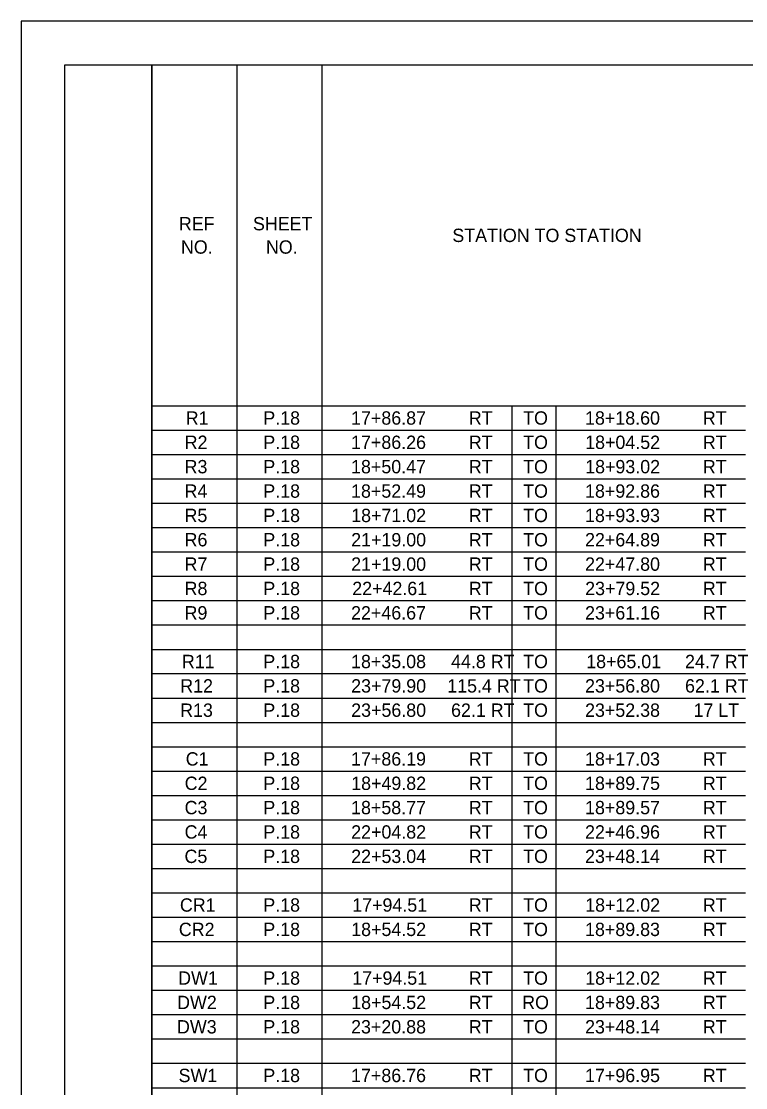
# Model space of a CAD drawing. Extents: x 0 to 34, y 0 to 22.
# Drawn here: x 0 to 8.32, y 9.75 to 22 of the extents above; entities that cross this region are included whole.
import ezdxf

# ---------------------------------------------------------------- set-up
doc = ezdxf.new("R2010")
doc.units = 0
for name, color, linetype in [('Default', 7, 'Continuous'), ('SH_Border', 7, 'Continuous'), ('SH_Cut_Line', 7, 'Continuous')]:
    doc.layers.add(name, color=color, linetype=linetype)

msp = doc.modelspace()

# ---------------------------------------------------------------- linework, layer by layer
at = {"layer": 'Default'}
for p, q in [((1.5, 21.5), (4.884, 21.5)), ((1.5, 21.5), (1.5, 21.22)), ((2.476, 21.5), (2.476, 21.22)), ((3.452, 21.5), (3.452, 21.22)), ((4.884, 21.5), (5.631, 21.5)), ((5.631, 21.5), (8.318, 21.5)), ((1.5, 21.22), (1.5, 20.941)), ((2.476, 21.22), (2.476, 20.941)), ((3.452, 21.22), (3.452, 20.941)), ((1.5, 20.941), (1.5, 20.661)), ((2.476, 20.941), (2.476, 20.661)), ((3.452, 20.941), (3.452, 20.661)), ((1.5, 20.661), (1.5, 20.381)), ((2.476, 20.661), (2.476, 20.381)), ((3.452, 20.661), (3.452, 20.381)), ((1.5, 20.381), (1.5, 20.101)), ((2.476, 20.381), (2.476, 20.101)), ((3.452, 20.381), (3.452, 20.101)), ((1.5, 20.101), (1.5, 19.822)), ((2.476, 20.101), (2.476, 19.822)), ((3.452, 20.101), (3.452, 19.822)), ((1.5, 19.822), (1.5, 19.542)), ((2.476, 19.822), (2.476, 19.542)), ((3.452, 19.822), (3.452, 19.542)), ((1.5, 19.542), (1.5, 18.982)), ((2.476, 19.542), (2.476, 18.982)), ((3.452, 19.542), (3.452, 18.982)), ((1.5, 18.982), (1.5, 18.143)), ((2.476, 18.982), (2.476, 18.143)), ((3.452, 18.982), (3.452, 18.143)), ((1.5, 18.143), (1.5, 17.864)), ((2.476, 18.143), (2.476, 17.864)), ((3.452, 18.143), (3.452, 17.864)), ((1.5, 17.864), (1.5, 17.304)), ((2.476, 17.864), (2.476, 17.304)), ((3.452, 17.864), (3.452, 17.304)), ((1.5, 17.584), (4.884, 17.584)), ((4.884, 17.584), (5.631, 17.584)), ((5.631, 17.584), (8.318, 17.584)), ((5.631, 17.584), (5.631, 17.304)), ((6.138, 17.584), (6.138, 17.304)), ((1.5, 17.304), (4.884, 17.304)), ((1.5, 17.304), (1.5, 17.024)), ((2.476, 17.304), (2.476, 17.024)), ((3.452, 17.304), (3.452, 17.024)), ((4.884, 17.304), (5.631, 17.304)), ((5.631, 17.304), (8.318, 17.304)), ((5.631, 17.304), (5.631, 17.024)), ((6.138, 17.304), (6.138, 17.024)), ((1.5, 17.024), (4.884, 17.024)), ((1.5, 17.024), (1.5, 15.905)), ((2.476, 17.024), (2.476, 15.905)), ((3.452, 17.024), (3.452, 15.905)), ((4.884, 17.024), (5.631, 17.024)), ((5.631, 17.024), (8.318, 17.024)), ((5.631, 17.024), (5.631, 15.905)), ((6.138, 17.024), (6.138, 15.905)), ((1.5, 16.745), (4.884, 16.745)), ((4.884, 16.745), (5.631, 16.745)), ((5.631, 16.745), (8.318, 16.745)), ((1.5, 16.465), (4.884, 16.465)), ((4.884, 16.465), (5.631, 16.465)), ((5.631, 16.465), (8.318, 16.465)), ((1.5, 16.185), (4.884, 16.185)), ((4.884, 16.185), (5.631, 16.185)), ((5.631, 16.185), (8.318, 16.185)), ((1.5, 15.905), (4.884, 15.905)), ((1.5, 15.905), (1.5, 15.626)), ((2.476, 15.905), (2.476, 15.626)), ((3.452, 15.905), (3.452, 15.626)), ((4.884, 15.905), (5.631, 15.905)), ((5.631, 15.905), (8.318, 15.905)), ((5.631, 15.905), (5.631, 15.626)), ((6.138, 15.905), (6.138, 15.626)), ((1.5, 15.626), (4.884, 15.626)), ((1.5, 15.626), (1.5, 15.066)), ((2.476, 15.626), (2.476, 15.066)), ((3.452, 15.626), (3.452, 15.066)), ((4.884, 15.626), (5.631, 15.626)), ((5.631, 15.626), (8.318, 15.626)), ((5.631, 15.626), (5.631, 15.066)), ((6.138, 15.626), (6.138, 15.066)), ((1.5, 15.346), (4.884, 15.346)), ((4.884, 15.346), (5.631, 15.346)), ((5.631, 15.346), (8.318, 15.346)), ((1.5, 15.066), (4.884, 15.066)), ((1.5, 15.066), (1.5, 14.507)), ((2.476, 15.066), (2.476, 14.507)), ((3.452, 15.066), (3.452, 14.507)), ((4.884, 15.066), (5.631, 15.066)), ((5.631, 15.066), (8.318, 15.066)), ((5.631, 15.066), (5.631, 14.507)), ((6.138, 15.066), (6.138, 14.507)), ((1.5, 14.786), (4.884, 14.786)), ((4.884, 14.786), (5.631, 14.786)), ((5.631, 14.786), (8.318, 14.786)), ((1.5, 14.507), (4.884, 14.507)), ((1.5, 14.507), (1.5, 14.227)), ((2.476, 14.507), (2.476, 14.227)), ((3.452, 14.507), (3.452, 14.227)), ((4.884, 14.507), (5.631, 14.507)), ((5.631, 14.507), (8.318, 14.507)), ((5.631, 14.507), (5.631, 14.227)), ((6.138, 14.507), (6.138, 14.227)), ((1.5, 14.227), (4.884, 14.227)), ((1.5, 14.227), (1.5, 13.668)), ((2.476, 14.227), (2.476, 13.668)), ((3.452, 14.227), (3.452, 13.668)), ((4.884, 14.227), (5.631, 14.227)), ((5.631, 14.227), (8.318, 14.227)), ((5.631, 14.227), (5.631, 13.668)), ((6.138, 14.227), (6.138, 13.668)), ((1.5, 13.947), (4.884, 13.947)), ((4.884, 13.947), (5.631, 13.947)), ((5.631, 13.947), (8.318, 13.947)), ((1.5, 13.668), (4.884, 13.668)), ((1.5, 13.668), (1.5, 13.388)), ((2.476, 13.668), (2.476, 13.388)), ((3.452, 13.668), (3.452, 13.388)), ((4.884, 13.668), (5.631, 13.668)), ((5.631, 13.668), (8.318, 13.668)), ((5.631, 13.668), (5.631, 13.388)), ((6.138, 13.668), (6.138, 13.388)), ((1.5, 13.388), (4.884, 13.388)), ((1.5, 13.388), (1.5, 12.549)), ((2.476, 13.388), (2.476, 12.549)), ((3.452, 13.388), (3.452, 12.549)), ((4.884, 13.388), (5.631, 13.388)), ((5.631, 13.388), (8.318, 13.388)), ((5.631, 13.388), (5.631, 12.549)), ((6.138, 13.388), (6.138, 12.549)), ((1.5, 13.108), (4.884, 13.108)), ((4.884, 13.108), (5.631, 13.108)), ((5.631, 13.108), (8.318, 13.108)), ((1.5, 12.828), (4.884, 12.828)), ((4.884, 12.828), (5.631, 12.828)), ((5.631, 12.828), (8.318, 12.828)), ((1.5, 12.549), (4.884, 12.549)), ((1.5, 12.549), (1.5, 11.989)), ((2.476, 12.549), (2.476, 11.989)), ((3.452, 12.549), (3.452, 11.989)), ((4.884, 12.549), (5.631, 12.549)), ((5.631, 12.549), (8.318, 12.549)), ((5.631, 12.549), (5.631, 11.989)), ((6.138, 12.549), (6.138, 11.989)), ((1.5, 12.269), (4.884, 12.269)), ((4.884, 12.269), (5.631, 12.269)), ((5.631, 12.269), (8.318, 12.269)), ((1.5, 11.989), (4.884, 11.989)), ((1.5, 11.989), (1.5, 11.15)), ((2.476, 11.989), (2.476, 11.15)), ((3.452, 11.989), (3.452, 11.15)), ((4.884, 11.989), (5.631, 11.989)), ((5.631, 11.989), (8.318, 11.989)), ((5.631, 11.989), (5.631, 11.15)), ((6.138, 11.989), (6.138, 11.15)), ((1.5, 11.709), (4.884, 11.709)), ((4.884, 11.709), (5.631, 11.709)), ((5.631, 11.709), (8.318, 11.709)), ((1.5, 11.43), (4.884, 11.43)), ((4.884, 11.43), (5.631, 11.43)), ((5.631, 11.43), (8.318, 11.43)), ((1.5, 11.15), (4.884, 11.15)), ((1.5, 11.15), (1.5, 10.591)), ((2.476, 11.15), (2.476, 10.591)), ((3.452, 11.15), (3.452, 10.591)), ((4.884, 11.15), (5.631, 11.15)), ((5.631, 11.15), (8.318, 11.15)), ((5.631, 11.15), (5.631, 10.591)), ((6.138, 11.15), (6.138, 10.591)), ((1.5, 10.87), (4.884, 10.87)), ((4.884, 10.87), (5.631, 10.87)), ((5.631, 10.87), (8.318, 10.87)), ((1.5, 10.591), (4.884, 10.591)), ((1.5, 10.591), (1.5, 9.751)), ((2.476, 10.591), (2.476, 9.751)), ((3.452, 10.591), (3.452, 9.751)), ((4.884, 10.591), (5.631, 10.591)), ((5.631, 10.591), (8.318, 10.591)), ((5.631, 10.591), (5.631, 9.751)), ((6.138, 10.591), (6.138, 9.751)), ((1.5, 10.311), (4.884, 10.311)), ((4.884, 10.311), (5.631, 10.311)), ((5.631, 10.311), (8.318, 10.311)), ((1.5, 10.031), (4.884, 10.031)), ((4.884, 10.031), (5.631, 10.031)), ((5.631, 10.031), (8.318, 10.031)), ((1.5, 9.751), (4.884, 9.751)), ((1.5, 9.751), (1.5, 9.192)), ((2.476, 9.751), (2.476, 9.192)), ((3.452, 9.751), (3.452, 9.192)), ((4.884, 9.751), (5.631, 9.751)), ((5.631, 9.751), (8.318, 9.751)), ((5.631, 9.751), (5.631, 9.192)), ((6.138, 9.751), (6.138, 9.192))]:
    msp.add_line(p, q, dxfattribs=at)
at = {"layer": 'SH_Border'}
for points in [[(0.5, 21.5), (1.5, 21.5), (1.5, 0.5), (0.5, 0.5)], [(1.5, 21.5), (33.5, 21.5), (33.5, 0.5), (1.5, 0.5)]]:
    msp.add_lwpolyline(points, close=True, dxfattribs=at)
at = {"layer": 'SH_Cut_Line'}
msp.add_lwpolyline([(0, 0), (34, 0), (34, 22), (0, 22)], close=True, dxfattribs=at)

# ---------------------------------------------------------------- texts
at = {"layer": 'Default'}
for s, height, p in [('REF', 0.1532, (1.809, 19.599)), ('SHEET', 0.1532, (2.66, 19.599)), ('STATION TO STATION', 0.15319, (4.95, 19.465)), ('NO.', 0.1532, (1.833, 19.331)), ('NO.', 0.1532, (2.809, 19.331)), ('R1', 0.1532, (1.888, 17.367)), ('P.18', 0.1532, (2.779, 17.367)), ('17+86.87', 0.1532, (3.787, 17.367)), ('RT', 0.1532, (5.139, 17.367)), ('TO', 0.1532, (5.763, 17.367)), ('18+18.60', 0.1532, (6.474, 17.367)), ('RT', 0.1532, (7.826, 17.367)), ('R2', 0.1532, (1.876, 17.088)), ('P.18', 0.1532, (2.779, 17.088)), ('17+86.26', 0.1532, (3.787, 17.088)), ('RT', 0.1532, (5.139, 17.088)), ('TO', 0.1532, (5.763, 17.088)), ('18+04.52', 0.1532, (6.475, 17.088)), ('RT', 0.1532, (7.826, 17.088)), ('R3', 0.1532, (1.875, 16.808)), ('P.18', 0.1532, (2.779, 16.808)), ('18+50.47', 0.1532, (3.787, 16.808)), ('RT', 0.1532, (5.139, 16.808)), ('TO', 0.1532, (5.763, 16.808)), ('18+93.02', 0.1532, (6.475, 16.808)), ('RT', 0.1532, (7.826, 16.808)), ('R4', 0.1532, (1.875, 16.528)), ('P.18', 0.1532, (2.779, 16.528)), ('18+52.49', 0.1532, (3.787, 16.528)), ('RT', 0.1532, (5.139, 16.528)), ('TO', 0.1532, (5.763, 16.528)), ('18+92.86', 0.1532, (6.474, 16.528)), ('RT', 0.1532, (7.826, 16.528)), ('R5', 0.1532, (1.874, 16.248)), ('P.18', 0.1532, (2.779, 16.248)), ('18+71.02', 0.1532, (3.788, 16.248)), ('RT', 0.1532, (5.139, 16.248)), ('TO', 0.1532, (5.763, 16.248)), ('18+93.93', 0.1532, (6.474, 16.248)), ('RT', 0.1532, (7.826, 16.248)), ('R6', 0.1532, (1.875, 15.969)), ('P.18', 0.1532, (2.779, 15.969)), ('21+19.00', 0.1532, (3.788, 15.969)), ('RT', 0.1532, (5.139, 15.969)), ('TO', 0.1532, (5.763, 15.969)), ('22+64.89', 0.1532, (6.474, 15.969)), ('RT', 0.1532, (7.826, 15.969)), ('R7', 0.1532, (1.875, 15.689)), ('P.18', 0.1532, (2.779, 15.689)), ('21+19.00', 0.1532, (3.788, 15.689)), ('RT', 0.1532, (5.139, 15.689)), ('TO', 0.1532, (5.763, 15.689)), ('22+47.80', 0.1532, (6.474, 15.689)), ('RT', 0.1532, (7.826, 15.689)), ('R8', 0.1532, (1.875, 15.409)), ('P.18', 0.1532, (2.779, 15.409)), ('22+42.61', 0.1532, (3.8, 15.409)), ('RT', 0.1532, (5.139, 15.409)), ('TO', 0.1532, (5.763, 15.409)), ('23+79.52', 0.1532, (6.475, 15.409)), ('RT', 0.1532, (7.826, 15.409)), ('R9', 0.1532, (1.875, 15.129)), ('P.18', 0.1532, (2.779, 15.129)), ('22+46.67', 0.1532, (3.787, 15.129)), ('RT', 0.1532, (5.139, 15.129)), ('TO', 0.1532, (5.763, 15.129)), ('23+61.16', 0.1532, (6.474, 15.129)), ('RT', 0.1532, (7.826, 15.129)), ('R11', 0.1532, (1.844, 14.57)), ('P.18', 0.1532, (2.779, 14.57)), ('18+35.08', 0.1532, (3.787, 14.57)), ('44.8 RT', 0.1532, (4.935, 14.57)), ('TO', 0.1532, (5.763, 14.57)), ('18+65.01', 0.1532, (6.487, 14.57)), ('24.7 RT', 0.1532, (7.622, 14.57)), ('R12', 0.1532, (1.825, 14.29)), ('P.18', 0.1532, (2.779, 14.29)), ('23+79.90', 0.1532, (3.788, 14.29)), ('115.4 RT', 0.1532, (4.891, 14.29)), ('TO', 0.1532, (5.763, 14.29)), ('23+56.80', 0.1532, (6.474, 14.29)), ('62.1 RT', 0.1532, (7.622, 14.29)), ('R13', 0.1532, (1.824, 14.011)), ('P.18', 0.1532, (2.779, 14.011)), ('23+56.80', 0.1532, (3.788, 14.011)), ('62.1 RT', 0.1532, (4.935, 14.011)), ('TO', 0.1532, (5.763, 14.011)), ('23+52.38', 0.1532, (6.474, 14.011)), ('17 LT', 0.1532, (7.719, 14.011)), ('C1', 0.1532, (1.888, 13.451)), ('P.18', 0.1532, (2.779, 13.451)), ('17+86.19', 0.1532, (3.787, 13.451)), ('RT', 0.1532, (5.139, 13.451)), ('TO', 0.1532, (5.763, 13.451)), ('18+17.03', 0.1532, (6.474, 13.451)), ('RT', 0.1532, (7.826, 13.451)), ('C2', 0.1532, (1.876, 13.171)), ('P.18', 0.1532, (2.779, 13.171)), ('18+49.82', 0.1532, (3.788, 13.171)), ('RT', 0.1532, (5.139, 13.171)), ('TO', 0.1532, (5.763, 13.171)), ('18+89.75', 0.1532, (6.474, 13.171)), ('RT', 0.1532, (7.826, 13.171)), ('C3', 0.1532, (1.875, 12.892)), ('P.18', 0.1532, (2.779, 12.892)), ('18+58.77', 0.1532, (3.787, 12.892)), ('RT', 0.1532, (5.139, 12.892)), ('TO', 0.1532, (5.763, 12.892)), ('18+89.57', 0.1532, (6.474, 12.892)), ('RT', 0.1532, (7.826, 12.892)), ('C4', 0.1532, (1.875, 12.612)), ('P.18', 0.1532, (2.779, 12.612)), ('22+04.82', 0.1532, (3.788, 12.612)), ('RT', 0.1532, (5.139, 12.612)), ('TO', 0.1532, (5.763, 12.612)), ('22+46.96', 0.1532, (6.474, 12.612)), ('RT', 0.1532, (7.826, 12.612)), ('C5', 0.1532, (1.874, 12.332)), ('P.18', 0.1532, (2.779, 12.332)), ('22+53.04', 0.1532, (3.788, 12.332)), ('RT', 0.1532, (5.139, 12.332)), ('TO', 0.1532, (5.763, 12.332)), ('23+48.14', 0.1532, (6.474, 12.332)), ('RT', 0.1532, (7.826, 12.332)), ('CR1', 0.1532, (1.821, 11.773)), ('P.18', 0.1532, (2.779, 11.773)), ('17+94.51', 0.1532, (3.8, 11.773)), ('RT', 0.1532, (5.139, 11.773)), ('TO', 0.1532, (5.763, 11.773)), ('18+12.02', 0.1532, (6.475, 11.773)), ('RT', 0.1532, (7.826, 11.773)), ('CR2', 0.1532, (1.809, 11.493)), ('P.18', 0.1532, (2.779, 11.493)), ('18+54.52', 0.1532, (3.788, 11.493)), ('RT', 0.1532, (5.139, 11.493)), ('TO', 0.1532, (5.763, 11.493)), ('18+89.83', 0.1532, (6.474, 11.493)), ('RT', 0.1532, (7.826, 11.493)), ('DW1', 0.1532, (1.801, 10.934)), ('P.18', 0.1532, (2.779, 10.934)), ('17+94.51', 0.1532, (3.8, 10.934)), ('RT', 0.1532, (5.139, 10.934)), ('TO', 0.1532, (5.763, 10.934)), ('18+12.02', 0.1532, (6.475, 10.934)), ('RT', 0.1532, (7.826, 10.934)), ('DW2', 0.1532, (1.789, 10.654)), ('P.18', 0.1532, (2.779, 10.654)), ('18+54.52', 0.1532, (3.788, 10.654)), ('RT', 0.1532, (5.139, 10.654)), ('RO', 0.1532, (5.752, 10.654)), ('18+89.83', 0.1532, (6.474, 10.654)), ('RT', 0.1532, (7.826, 10.654)), ('DW3', 0.1532, (1.788, 10.374)), ('P.18', 0.1532, (2.779, 10.374)), ('23+20.88', 0.1532, (3.787, 10.374)), ('RT', 0.1532, (5.139, 10.374)), ('TO', 0.1532, (5.763, 10.374)), ('23+48.14', 0.1532, (6.474, 10.374)), ('RT', 0.1532, (7.826, 10.374)), ('SW1', 0.1532, (1.806, 9.815)), ('P.18', 0.1532, (2.779, 9.815)), ('17+86.76', 0.1532, (3.787, 9.815)), ('RT', 0.1532, (5.139, 9.815)), ('TO', 0.1532, (5.763, 9.815)), ('17+96.95', 0.1532, (6.474, 9.815)), ('RT', 0.1532, (7.826, 9.815))]:
    msp.add_text(s, height=height, dxfattribs=at).set_placement(p)

doc.saveas('drawing.dxf')
